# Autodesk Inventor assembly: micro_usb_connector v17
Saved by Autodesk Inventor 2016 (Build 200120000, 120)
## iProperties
Created: 2018-05
Part Number: micro_usb_connector v17
Document SubType Name: Assembly
Designer: Administrator
Title: micro_usb_connector v17
Author: Administrator
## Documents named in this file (5)
- c:\worker\convert-fusion-mar-2018\tmp\job-1\16\output\files\8c58ff39-88bb-4352-afd9-60265520bae5\micro_usb_connector v17.iam
- c:\worker\convert-fusion-mar-2018\tmp\job-1\16\output\files\8c58ff39-88bb-4352-afd9-60265520bae5\shield.ipt
- c:\worker\convert-fusion-mar-2018\tmp\job-1\16\output\files\8c58ff39-88bb-4352-afd9-60265520bae5\socket_housing.ipt
- c:\worker\convert-fusion-mar-2018\tmp\job-1\16\output\files\8c58ff39-88bb-4352-afd9-60265520bae5\socket_plate.ipt
- c:\worker\convert-fusion-mar-2018\tmp\job-1\16\output\files\8c58ff39-88bb-4352-afd9-60265520bae5\terminal.ipt
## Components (8 placed, 4 different names)
1. shield:1
2. socket_housing:1
3. socket_plate:1
4. terminal:1
5. terminal:2
6. terminal:3
7. terminal:4
8. terminal:5
